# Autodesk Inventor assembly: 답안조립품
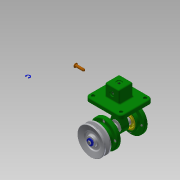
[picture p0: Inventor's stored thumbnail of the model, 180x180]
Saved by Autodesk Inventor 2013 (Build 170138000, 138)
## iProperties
Created: 2017-08
Part Number: 답안조립품
Document SubType Name: Assembly
Designer: Administrator
Author: Administrator
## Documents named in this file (18)
- C:\Users\Administrator\Desktop\470807V1011\답안조립품.iam
- C:\Users\Administrator\Desktop\470807V1011\본체.ipt
- C:\Users\Administrator\Desktop\470807V1011\공용부품\E-링.ipt
- C:\Users\Administrator\Desktop\470807V1011\공용부품\V-벨트풀리.ipt
- C:\Users\Administrator\Desktop\470807V1011\공용부품\덮개.ipt
- C:\Users\Administrator\Desktop\470807V1011\공용부품\뒤커버.ipt
- C:\Users\Administrator\Desktop\470807V1011\공용부품\링크.ipt
- C:\Users\Administrator\Desktop\470807V1011\공용부품\베어링 17 x 40 x 12.ipt
- C:\Users\Administrator\Desktop\470807V1011\공용부품\볼트 M4 x 8.ipt
- C:\Users\Administrator\Desktop\470807V1011\공용부품\볼트 M4 x 10.ipt
- C:\Users\Administrator\Desktop\470807V1011\공용부품\슬라이더.ipt
- C:\Users\Administrator\Desktop\470807V1011\공용부품\앞커버.ipt
- C:\Users\Administrator\Desktop\470807V1011\공용부품\오일 실 17 30 8.ipt
- C:\Users\Administrator\Desktop\470807V1011\공용부품\와셔 4x16.ipt
- C:\Users\Administrator\Desktop\470807V1011\공용부품\클레비스 핀 6 x 22.ipt
- 클레비스 핀 6 x 22.ipt
- C:\Users\Administrator\Desktop\470807V1011\공용부품\키 4 x 4 x 12.ipt
- C:\Users\Administrator\Desktop\470807V1011\공용부품\편심축.ipt
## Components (2 placed, 2 different names)
1. E-링:1
2. V-벨트풀리:1
